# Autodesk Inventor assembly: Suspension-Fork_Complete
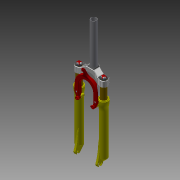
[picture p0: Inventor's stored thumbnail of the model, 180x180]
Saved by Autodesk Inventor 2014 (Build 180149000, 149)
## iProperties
Shininess: 64.0
Length Units: 11272
Angle Units: 11279
Time Units: 11290
Mass Units: 11286
Length Display Precision: 3
Angle Display Precision: 2
Compacted: True
Created: 2001-11
Part Number: Suspension-Fork_Complete
Document SubType Name: Assembly
Designer: Autodesk, Inc.
Mass: 668.12 g
Surface Area: 4148.96 cm^2
Volume: 661.98 cm^3
Density: 1.00928 g/cm^3
Density: 0.0
Volumn: 0.0
Area: 0.0
PropertySet Name: Model Information
Control State: 0
Master: False
Checked Out: False
Author: Autodesk, Inc.
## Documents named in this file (15)
- C:\Users\iTools\Desktop\tutorial files\Assembly FEA 3\Suspension-Fork_Complete.iam
- C:\Users\iTools\Desktop\tutorial files\Assembly FEA 3\Components\Fork-Slider_MIR.ipt
- C:\Users\iTools\Desktop\tutorial files\Assembly FEA 3\Components\Fork-Piston_MIR.ipt
- C:\Users\iTools\Desktop\tutorial files\Assembly FEA 3\Components\Fork-Tube_MIR.ipt
- C:\Users\iTools\Desktop\tutorial files\Assembly FEA 3\Components\Fork-Damper_MIR.ipt
- C:\Users\iTools\Desktop\tutorial files\Assembly FEA 3\Components\Dial-Elastomer.iam
- C:\Users\iTools\Desktop\tutorial files\Assembly FEA 3\Components\Head Tube.ipt
- C:\Users\iTools\Desktop\tutorial files\Assembly FEA 3\Components\Fork-Slider.ipt
- C:\Users\iTools\Desktop\tutorial files\Assembly FEA 3\Components\Fork-Piston.ipt
- C:\Users\iTools\Desktop\tutorial files\Assembly FEA 3\Components\Fork-Crown.ipt
- C:\Users\iTools\Desktop\tutorial files\Assembly FEA 3\Components\Fork-Brace.ipt
- C:\Users\iTools\Desktop\tutorial files\Assembly FEA 3\Components\Fork-Tube.ipt
- C:\Users\iTools\Desktop\tutorial files\Assembly FEA 3\Components\Fork-Damper.ipt
- C:\Users\iTools\Desktop\tutorial files\Assembly FEA 3\Standard Parts\UNI 5933 - M4 x 12.ipt
- C:\Users\iTools\Desktop\tutorial files\Assembly FEA 3\Standard Parts\NF E 25-125 - M3 x 10.ipt
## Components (19 placed, 14 different names)
1. Fork-Crown:1 — Mate:7, Tangent:1, Angle:1, Mate:10, Insert:15, Mate:11, Insert:25, Insert:26, Insert:27, Insert:28
2. Head Tube:1 — Mate:7, Tangent:1
3. Fork-Brace:1 — Insert:23, Insert:24
4. Dial-Elastomer [sub-assembly] — Insert:19
5. Fork-Slider:1 — Insert:2, Angle:1, Mate:10, Mate:11
6. Fork-Piston:1 — Insert:2
7. UNI 5933 M4 x 12:1 — Insert:23
8. NF E 25-125 M3 x 10:1 — Insert:25
9. NF E 25-125 M3 x 10:2 — Insert:26
10. Fork-Tube:1 — Insert:15, Insert:16, Insert:19
11. Fork-Damper:1 — Insert:16
12. Dial-Elastomer:2 [sub-assembly] — Insert:21
13. Fork-Slider_MIR:1 — Insert:20
14. Fork-Piston_MIR:1 — Insert:20
15. NF E 25-125 M3 x 10:3 — Insert:28
16. NF E 25-125 M3 x 10:4 — Insert:27
17. UNI 5933 M4 x 12:2 — Insert:24
18. Fork-Tube_MIR:1 — Insert:21, Insert:22
19. Fork-Damper_MIR:1 — Insert:22
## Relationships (18: Insert 13, Mate 3, Tangent 1, Angle 1)
- Insert:2: Fork-Slider:1 ↔ Fork-Piston:1
- Mate:7: Fork-Crown:1 ↔ Head Tube:1
- Tangent:1: Fork-Crown:1 ↔ Head Tube:1
- Angle:1: Fork-Crown:1 ↔ Fork-Slider:1
- Mate:10: Fork-Crown:1 ↔ Fork-Slider:1
- Insert:15: Fork-Crown:1 ↔ Fork-Tube:1
- Insert:16: Fork-Tube:1 ↔ Fork-Damper:1
- Mate:11: Fork-Crown:1 ↔ Fork-Slider:1
- Insert:19: Dial-Elastomer ↔ Fork-Tube:1
- Insert:20: Fork-Slider_MIR:1 ↔ Fork-Piston_MIR:1
- Insert:21: Dial-Elastomer:2 ↔ Fork-Tube_MIR:1
- Insert:22: Fork-Tube_MIR:1 ↔ Fork-Damper_MIR:1
- Insert:23: Fork-Brace:1 ↔ UNI 5933 M4 x 12:1
- Insert:24: Fork-Brace:1 ↔ UNI 5933 M4 x 12:2
- Insert:25: Fork-Crown:1 ↔ NF E 25-125 M3 x 10:1
- Insert:26: Fork-Crown:1 ↔ NF E 25-125 M3 x 10:2
- Insert:27: Fork-Crown:1 ↔ NF E 25-125 M3 x 10:4
- Insert:28: Fork-Crown:1 ↔ NF E 25-125 M3 x 10:3
